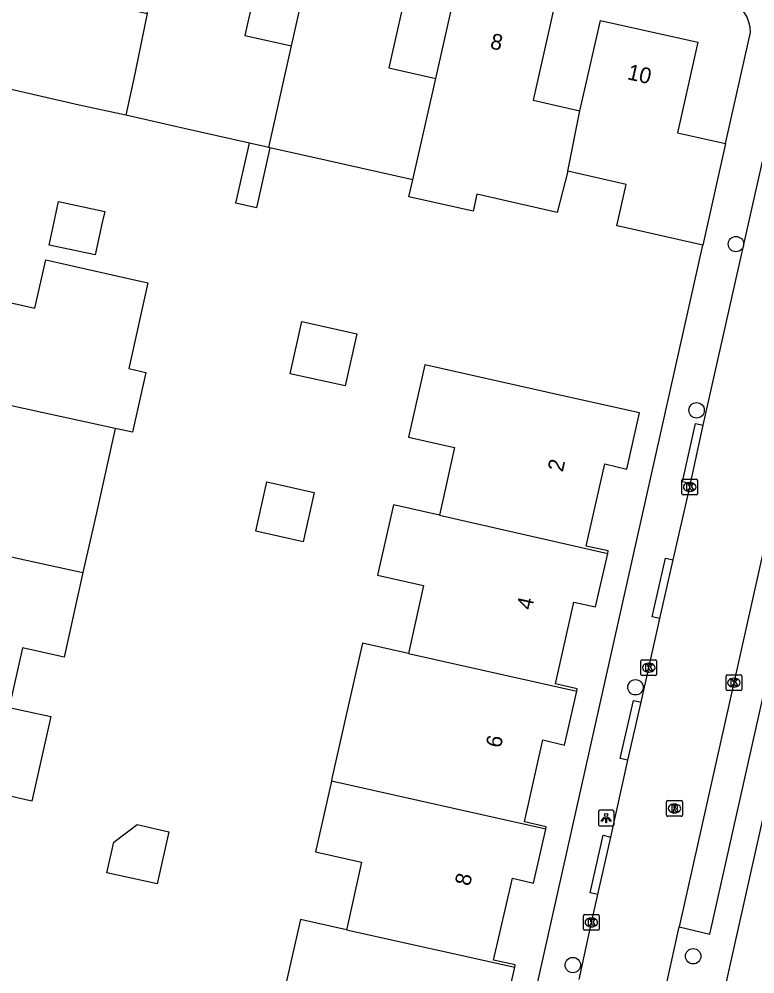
# Model space of a CAD drawing. Extents: x 161771 to 163125, y 382479 to 383177.
# Drawn here: x 162596.6 to 162643.4, y 382630.1 to 382690.8 of the extents above; entities that cross this region are included whole.
import ezdxf

# ---------------------------------------------------------------- set-up
doc = ezdxf.new("R2010")
doc.units = 0
for name, color, linetype in [('IMGEO_Boom', 7, 'Continuous'), ('IMGEO_Kolk', 7, 'Continuous'), ('IMGEO_Lichtpunt', 7, 'Continuous'), ('IMGEO_Pand', 7, 'Continuous'), ('IMGEO_Pand_nummerreeks', 7, 'Continuous'), ('IMGEO_Rijbaan_lokaal_open', 7, 'Continuous'), ('IMGEO_Rioolput', 7, 'Continuous'), ('IMGEO_Voetpad_open', 7, 'Continuous')]:
    doc.layers.add(name, color=color, linetype=linetype)

msp = doc.modelspace()

# ---------------------------------------------------------------- linework, layer by layer
at = {"layer": 'IMGEO_Boom'}
for centre in [(162642.196, 382676.509), (162639.695, 382665.934), (162635.808, 382648.312), (162639.474, 382631.202), (162631.823, 382630.642)]:
    msp.add_circle(centre, 0.489, dxfattribs=at)
at = {"layer": 'IMGEO_Kolk'}
for p, q in [((162638.756, 382660.626), (162638.756, 382661.478)), ((162638.831, 382661.552), (162639.683, 382661.552)), ((162639.244, 382661.332), (162639.269, 382661.332)), ((162639.757, 382661.478), (162639.757, 382660.626)), ((162639.683, 382660.552), (162638.831, 382660.552)), ((162639.267, 382660.772), (162639.242, 382660.772)), ((162636.153, 382649.136), (162636.153, 382649.988)), ((162636.228, 382650.062), (162637.08, 382650.062)), ((162636.641, 382649.842), (162636.666, 382649.842)), ((162637.154, 382649.988), (162637.154, 382649.136)), ((162637.08, 382649.062), (162636.228, 382649.062)), ((162636.664, 382649.282), (162636.639, 382649.282)), ((162641.563, 382648.178), (162641.563, 382649.03)), ((162641.638, 382649.104), (162642.49, 382649.104)), ((162642.564, 382649.03), (162642.564, 382648.178)), ((162642.051, 382648.884), (162642.076, 382648.884)), ((162642.49, 382648.104), (162641.638, 382648.104)), ((162642.074, 382648.324), (162642.049, 382648.324)), ((162632.501, 382632.927), (162632.501, 382633.779)), ((162632.576, 382633.853), (162633.428, 382633.853)), ((162633.502, 382633.779), (162633.502, 382632.927)), ((162632.989, 382633.633), (162633.014, 382633.633)), ((162633.428, 382632.853), (162632.576, 382632.853)), ((162633.012, 382633.073), (162632.987, 382633.073))]:
    msp.add_line(p, q, dxfattribs=at)
for points in [[(162638.756, 382660.626), (162638.756, 382661.478)], [(162638.831, 382661.552), (162639.683, 382661.552)], [(162639.077, 382661.252), (162639.2, 382661.252), (162639.2, 382661.101), (162639.33, 382661.252), (162639.494, 382661.252), (162639.348, 382661.101), (162639.501, 382660.852), (162639.349, 382660.852), (162639.264, 382661.016), (162639.2, 382660.949), (162639.2, 382660.852), (162639.077, 382660.852), (162639.077, 382661.252)], [(162639.757, 382661.478), (162639.757, 382660.626)], [(162639.683, 382660.552), (162638.831, 382660.552)], [(162636.153, 382649.136), (162636.153, 382649.988)], [(162636.228, 382650.062), (162637.08, 382650.062)], [(162636.474, 382649.762), (162636.597, 382649.762), (162636.597, 382649.611), (162636.727, 382649.762), (162636.891, 382649.762), (162636.745, 382649.611), (162636.898, 382649.362), (162636.746, 382649.362), (162636.661, 382649.526), (162636.597, 382649.459), (162636.597, 382649.362), (162636.474, 382649.362), (162636.474, 382649.762)], [(162637.154, 382649.988), (162637.154, 382649.136)], [(162637.08, 382649.062), (162636.228, 382649.062)], [(162641.563, 382648.178), (162641.563, 382649.03)], [(162641.638, 382649.104), (162642.49, 382649.104)], [(162642.564, 382649.03), (162642.564, 382648.178)], [(162641.884, 382648.804), (162642.007, 382648.804), (162642.007, 382648.653), (162642.137, 382648.804), (162642.301, 382648.804), (162642.155, 382648.653), (162642.308, 382648.404), (162642.156, 382648.404), (162642.071, 382648.568), (162642.007, 382648.501), (162642.007, 382648.404), (162641.884, 382648.404), (162641.884, 382648.804)], [(162642.49, 382648.104), (162641.638, 382648.104)], [(162632.501, 382632.927), (162632.501, 382633.779)], [(162632.576, 382633.853), (162633.428, 382633.853)], [(162633.502, 382633.779), (162633.502, 382632.927)], [(162632.822, 382633.553), (162632.945, 382633.553), (162632.945, 382633.402), (162633.075, 382633.553), (162633.239, 382633.553), (162633.093, 382633.402), (162633.246, 382633.153), (162633.094, 382633.153), (162633.009, 382633.317), (162632.945, 382633.25), (162632.945, 382633.153), (162632.822, 382633.153), (162632.822, 382633.553)], [(162633.428, 382632.853), (162632.576, 382632.853)]]:
    msp.add_lwpolyline(points, dxfattribs=at)
for centre, start, end in [((162638.833, 382661.476), 91.55205, 178.44795), ((162638.833, 382661.476), 91.55205, 178.44795), ((162639.681, 382661.476), 1.55205, 88.44795), ((162639.681, 382661.476), 1.55205, 88.44795), ((162638.833, 382660.628), 181.55205, 268.44795), ((162638.833, 382660.628), 181.55205, 268.44795), ((162639.681, 382660.628), 271.55205, 358.44795), ((162639.681, 382660.628), 271.55205, 358.44795), ((162636.23, 382649.986), 91.55205, 178.44795), ((162636.23, 382649.986), 91.55205, 178.44795), ((162637.078, 382649.986), 1.55205, 88.44795), ((162637.078, 382649.986), 1.55205, 88.44795), ((162636.23, 382649.138), 181.55205, 268.44795), ((162636.23, 382649.138), 181.55205, 268.44795), ((162637.078, 382649.138), 271.55205, 358.44795), ((162637.078, 382649.138), 271.55205, 358.44795), ((162641.64, 382649.028), 91.55205, 178.44795), ((162641.64, 382649.028), 91.55205, 178.44795), ((162642.488, 382649.028), 1.55205, 88.44795), ((162642.488, 382649.028), 1.55205, 88.44795), ((162641.64, 382648.18), 181.55205, 268.44795), ((162641.64, 382648.18), 181.55205, 268.44795), ((162642.488, 382648.18), 271.55205, 358.44795), ((162642.488, 382648.18), 271.55205, 358.44795), ((162632.578, 382633.777), 91.55205, 178.44795), ((162632.578, 382633.777), 91.55205, 178.44795), ((162633.426, 382633.777), 1.55205, 88.44795), ((162633.426, 382633.777), 1.55205, 88.44795), ((162632.578, 382632.929), 181.55205, 268.44795), ((162632.578, 382632.929), 181.55205, 268.44795), ((162633.426, 382632.929), 271.55205, 358.44795), ((162633.426, 382632.929), 271.55205, 358.44795)]:
    msp.add_arc(centre, 0.0765, start, end, dxfattribs=at)
for centre, major_axis, ratio, start_param, end_param in [((162639.243, 382661.052), (-0.387, 0.002), 0.722429, 4.712389, 7.853982), ((162639.268, 382661.052), (-0.39, 0.002), 0.717154, 1.570796, 4.712389), ((162636.64, 382649.562), (-0.387, 0.002), 0.722429, 4.712389, 7.853982), ((162636.665, 382649.562), (-0.39, 0.002), 0.717154, 1.570796, 4.712389), ((162642.05, 382648.604), (-0.387, 0.002), 0.722429, 4.712389, 7.853982), ((162642.075, 382648.604), (-0.39, 0.002), 0.717154, 1.570796, 4.712389), ((162632.988, 382633.353), (-0.387, 0.002), 0.722429, 4.712389, 7.853982), ((162633.013, 382633.353), (-0.39, 0.002), 0.717154, 1.570796, 4.712389)]:
    msp.add_ellipse(centre, major_axis=major_axis, ratio=ratio, start_param=start_param, end_param=end_param, dxfattribs=at)
at = {"layer": 'IMGEO_Lichtpunt'}
for p, q in [((162634.35, 382640.492), (162633.542, 382640.492)), ((162634.35, 382640.492), (162633.542, 382640.492)), ((162633.448, 382640.397), (162633.448, 382639.59)), ((162633.448, 382640.397), (162633.448, 382639.59)), ((162634.444, 382639.59), (162634.444, 382640.397)), ((162634.444, 382639.59), (162634.444, 382640.397)), ((162633.542, 382639.496), (162634.35, 382639.496)), ((162633.542, 382639.496), (162634.35, 382639.496))]:
    msp.add_line(p, q, dxfattribs=at)
for points in [[(162633.822, 382640.061), (162633.861, 382640.033), (162633.673, 382639.771), (162633.635, 382639.798), (162633.822, 382640.061)], [(162633.924, 382640.013), (162633.971, 382640.013), (162633.971, 382639.691), (162633.924, 382639.691), (162633.924, 382640.013)], [(162634.034, 382640.033), (162634.072, 382640.06), (162634.259, 382639.798), (162634.22, 382639.77), (162634.034, 382640.033)]]:
    msp.add_lwpolyline(points, dxfattribs=at)
msp.add_circle((162633.947, 382640.195), 0.0994, dxfattribs=at)
for centre, start, end in [((162633.542, 382640.397), 90, 180), ((162633.542, 382640.397), 90, 180), ((162634.35, 382640.397), 0, 90), ((162634.35, 382640.397), 0, 90), ((162633.542, 382639.59), 180, 270), ((162633.542, 382639.59), 180, 270), ((162634.35, 382639.59), 270, 0), ((162634.35, 382639.59), 270, 360)]:
    msp.add_arc(centre, 0.0946, start, end, dxfattribs=at)
at = {"layer": 'IMGEO_Pand'}
for points in [[(162603.399, 382684.706), (162600.45, 382685.345), (162594.797, 382686.643), (162594.699, 382689.434), (162596.882, 382699.004), (162603.087, 382697.607), (162601.791, 382691.852), (162604.757, 382691.184)], [(162604.757, 382691.184), (162605.818, 382695.894), (162606.053, 382696.939), (162612.267, 382695.54), (162610.971, 382689.785), (162613.937, 382689.117)], [(162613.937, 382689.117), (162615.233, 382694.872), (162621.428, 382693.477), (162620.132, 382687.722), (162623.107, 382687.052)], [(162623.107, 382687.052), (162624.403, 382692.807), (162630.598, 382691.412), (162629.302, 382685.657), (162632.278, 382684.987)], [(162604.757, 382691.184), (162604.04, 382687.661), (162603.972, 382687.346), (162603.399, 382684.706)], [(162632.278, 382684.987), (162632.463, 382685.809), (162633.574, 382690.742), (162639.768, 382689.347), (162638.472, 382683.592), (162641.523, 382682.919)], [(162612.506, 382682.656), (162613.937, 382689.117)], [(162621.652, 382680.596), (162623.107, 382687.052)], [(162631.507, 382681.145), (162632.278, 382684.987)], [(162611.262, 382682.936), (162607.109, 382683.871), (162603.399, 382684.706)], [(162612.567, 382682.642), (162611.708, 382678.825), (162610.402, 382679.119), (162611.262, 382682.936)], [(162612.506, 382682.656), (162611.262, 382682.936)], [(162612.567, 382682.642), (162612.506, 382682.656)], [(162621.652, 382680.596), (162616.27, 382681.808), (162612.567, 382682.642)], [(162641.523, 382682.919), (162640.083, 382676.445)], [(162631.507, 382681.145), (162630.834, 382678.528), (162625.727, 382679.679), (162625.484, 382678.594), (162621.408, 382679.51), (162621.652, 382680.596)], [(162640.083, 382676.445), (162635.206, 382677.544), (162634.62, 382677.676), (162635.214, 382680.311), (162631.507, 382681.145)], [(162601.909, 382677.883), (162601.457, 382675.816), (162598.524, 382676.451), (162598.972, 382678.519), (162599.124, 382679.223), (162602.062, 382678.587), (162601.909, 382677.883)], [(162596.228, 382666.205), (162590.471, 382667.496), (162591.858, 382673.719), (162597.625, 382672.43), (162598.314, 382675.503), (162603.193, 382674.408), (162604.813, 382674.044), (162603.592, 382668.591), (162604.675, 382668.349), (162603.823, 382664.536), (162602.737, 382664.776)], [(162613.854, 382668.264), (162614.598, 382671.586), (162618.088, 382670.805), (162617.344, 382667.483), (162613.854, 382668.264)], [(162634.044, 382656.83), (162634.079, 382656.988), (162632.683, 382657.301), (162633.855, 382662.52), (162635.256, 382662.18), (162636.059, 382665.767), (162631.194, 382666.866), (162622.411, 382668.834), (162621.378, 382664.219), (162624.306, 382663.563), (162623.385, 382659.455), (162623.341, 382659.26)], [(162602.737, 382664.776), (162596.228, 382666.205)], [(162602.737, 382664.776), (162601.537, 382659.418), (162600.683, 382655.607)], [(162611.675, 382658.242), (162612.379, 382661.383), (162615.381, 382660.71), (162614.677, 382657.569), (162611.675, 382658.242)], [(162623.341, 382659.26), (162620.415, 382659.924), (162619.41, 382655.437), (162622.338, 382654.781), (162621.412, 382650.653), (162621.37, 382650.466)], [(162623.341, 382659.26), (162634.044, 382656.83)], [(162594.169, 382657.033), (162598.046, 382656.184), (162600.683, 382655.607)], [(162632.071, 382648.06), (162632.107, 382648.215), (162630.72, 382648.525), (162631.885, 382653.732), (162633.272, 382653.422), (162634.044, 382656.83)], [(162600.683, 382655.607), (162599.48, 382650.236), (162596.846, 382650.827), (162596.018, 382647.129), (162595.993, 382647.019)], [(162621.37, 382650.466), (162618.443, 382651.124), (162617.439, 382646.645), (162616.514, 382642.517), (162616.475, 382642.343)], [(162621.37, 382650.466), (162632.071, 382648.06)], [(162630.1, 382639.284), (162630.134, 382639.44), (162628.761, 382639.753), (162629.915, 382644.964), (162631.296, 382644.634), (162632.071, 382648.06)], [(162595.993, 382647.019), (162598.632, 382646.447), (162597.428, 382641.073), (162594.794, 382641.664), (162594.531, 382640.489), (162593.939, 382637.845)], [(162616.475, 382642.343), (162615.468, 382637.853), (162618.396, 382637.197), (162617.469, 382633.06), (162617.431, 382632.893)], [(162630.1, 382639.284), (162616.475, 382642.343)], [(162604.132, 382639.579), (162606.147, 382639.127), (162605.402, 382635.802), (162602.2, 382636.519), (162602.637, 382638.467), (162604.132, 382639.579)], [(162628.128, 382630.514), (162628.162, 382630.666), (162626.78, 382630.957), (162627.982, 382636.162), (162629.327, 382635.861), (162630.1, 382639.284)], [(162617.431, 382632.893), (162614.502, 382633.544), (162613.498, 382629.061), (162616.426, 382628.405), (162615.499, 382624.268), (162615.464, 382624.113)], [(162617.431, 382632.893), (162628.128, 382630.514)], [(162626.166, 382621.738), (162626.197, 382621.876), (162624.82, 382622.196), (162625.983, 382627.376), (162627.363, 382627.066), (162628.128, 382630.514)]]:
    msp.add_lwpolyline(points, dxfattribs=at)
at = {"layer": 'IMGEO_Rijbaan_lokaal_open'}
for points in [[(162640.113, 382664.989), (162644.527, 382684.594), (162645.563, 382689.213)], [(162639.307, 382661.275), (162640.113, 382664.989)], [(162645.155, 382662.439), (162642.064, 382648.604), (162638.592, 382633.065)], [(162638.199, 382656.418), (162639.258, 382661.048), (162639.307, 382661.275)], [(162637.352, 382652.691), (162638.199, 382656.418)], [(162636.175, 382647.364), (162636.655, 382649.558), (162637.352, 382652.691)], [(162635.326, 382643.668), (162636.175, 382647.364)], [(162634.24, 382638.786), (162635.326, 382643.668)], [(162633.419, 382635.138), (162634.24, 382638.786)], [(162632.234, 382629.73), (162633.002, 382633.349), (162633.419, 382635.138)], [(162637.243, 382627.039), (162637.797, 382629.505), (162638.592, 382633.065)]]:
    msp.add_lwpolyline(points, dxfattribs=at)
at = {"layer": 'IMGEO_Rioolput'}
for p, q in [((162637.863, 382641.104), (162638.715, 382641.104)), ((162637.788, 382640.178), (162637.788, 382641.03)), ((162638.276, 382640.884), (162638.301, 382640.884)), ((162638.789, 382641.03), (162638.789, 382640.178)), ((162638.715, 382640.104), (162637.863, 382640.104)), ((162638.299, 382640.324), (162638.274, 382640.324))]:
    msp.add_line(p, q, dxfattribs=at)
for points in [[(162637.863, 382641.104), (162638.715, 382641.104)], [(162637.788, 382640.178), (162637.788, 382641.03)], [(162638.377, 382640.802), (162638.125, 382640.804), (162638.125, 382640.404)], [(162638.125, 382640.404), (162638.249, 382640.404), (162638.249, 382640.566), (162638.26, 382640.566)], [(162638.303, 382640.723), (162638.249, 382640.723), (162638.249, 382640.642)], [(162638.249, 382640.642), (162638.301, 382640.642)], [(162638.307, 382640.537), (162638.378, 382640.404), (162638.518, 382640.404), (162638.453, 382640.53)], [(162638.789, 382641.03), (162638.789, 382640.178)], [(162638.715, 382640.104), (162637.863, 382640.104)]]:
    msp.add_lwpolyline(points, dxfattribs=at)
for centre, radius, start, end in [((162637.865, 382641.028), 0.0765, 91.55205, 178.44795), ((162637.865, 382641.028), 0.0765, 91.55205, 178.44795), ((162638.713, 382641.028), 0.0765, 1.55205, 88.44795), ((162638.713, 382641.028), 0.0765, 1.55205, 88.44795), ((162638.259, 382640.513), 0.0533, 26.02933, 88.69889), ((162638.285, 382640.831), 0.19, 274.7715, 282.96867), ((162638.309, 382640.627), 0.0964, 77.00612, 93.18647), ((162638.323, 382640.684), 0.0378, 276.66336, 79.67722), ((162638.376, 382640.692), 0.109, 350.36119, 89.41601), ((162638.374, 382640.692), 0.112, 277.58423, 350.98172), ((162638.358, 382640.477), 0.108, 29.51342, 73.79051), ((162637.865, 382640.18), 0.0765, 181.55205, 268.44795), ((162637.865, 382640.18), 0.0765, 181.55205, 268.44795), ((162638.713, 382640.18), 0.0765, 271.55205, 358.44795), ((162638.713, 382640.18), 0.0765, 271.55205, 358.44795)]:
    msp.add_arc(centre, radius, start, end, dxfattribs=at)
for centre, major_axis, ratio, start_param, end_param in [((162638.275, 382640.604), (-0.387, 0.002), 0.722429, 4.712389, 7.853982), ((162638.3, 382640.604), (-0.39, 0.002), 0.717154, 1.570796, 4.712389)]:
    msp.add_ellipse(centre, major_axis=major_axis, ratio=ratio, start_param=start_param, end_param=end_param, dxfattribs=at)
at = {"layer": 'IMGEO_Voetpad_open'}
for points in [[(162641.523, 382682.919), (162643.112, 382689.963)], [(162621.402, 382592.881), (162622.207, 382596.532), (162640.083, 382676.445)], [(162639.307, 382661.275), (162638.807, 382661.385), (162639.625, 382665.096), (162640.113, 382664.989)], [(162649.296, 382664.072), (162636.509, 382606.935), (162636.331, 382606.03)], [(162638.592, 382633.065), (162640.531, 382632.6), (162647.131, 382661.99), (162645.155, 382662.439)], [(162637.352, 382652.691), (162636.865, 382652.801), (162637.712, 382656.528), (162638.199, 382656.418)], [(162635.326, 382643.668), (162634.839, 382643.779), (162635.688, 382647.475), (162636.175, 382647.364)], [(162633.419, 382635.138), (162632.932, 382635.247), (162633.753, 382638.895), (162634.24, 382638.786)]]:
    msp.add_lwpolyline(points, dxfattribs=at)
msp.add_arc((162641.019, 382690.023), 2.094, 358.35357, 72.14952, dxfattribs=at)

# ---------------------------------------------------------------- texts
at = {"layer": 'IMGEO_Pand_nummerreeks'}
for s, rotation, p in [('8', 347.30971, (162626.515, 382688.969)), ('10', 347.30773, (162635.236, 382687.005)), ('2', 77.36649, (162631.184, 382661.971)), ('4', 77.36649, (162629.215, 382653.191)), ('6', 77.36649, (162627.247, 382644.409)), ('8', 77.36649, (162625.28, 382635.63))]:
    msp.add_text(s, height=1, rotation=rotation, dxfattribs=at).set_placement(p)

doc.saveas('drawing.dxf')
